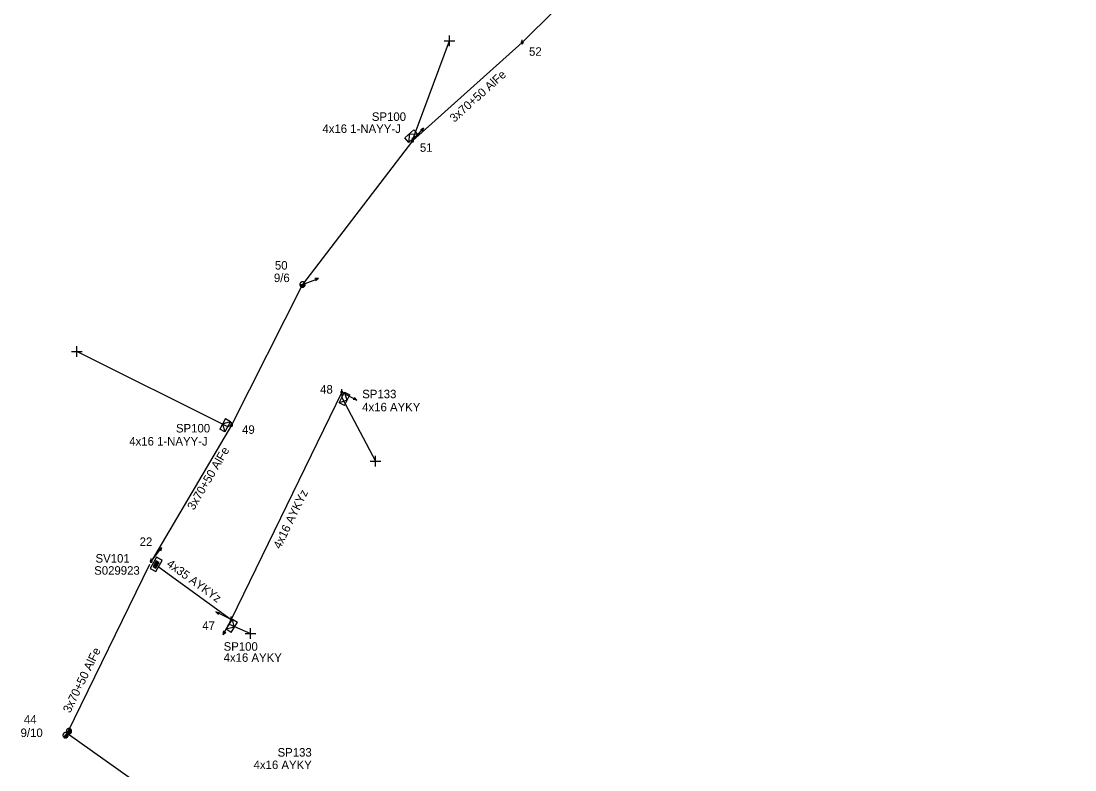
# Model space of a CAD drawing. Extents: x -788458 to -786145, y -1154772 to -1152372.
# Drawn here: x -787342.9 to -787219, y -1152727.5 to -1152639.6 of the extents above; entities that cross this region are included whole.
import ezdxf

# ---------------------------------------------------------------- set-up
doc = ezdxf.new("R2010")
doc.units = 0
for name, color, linetype in [('Vrstva 1', 7, 'Continuous'), ('Vrstva 12', 7, 'Continuous'), ('Vrstva 13', 7, 'Continuous'), ('Vrstva 14', 7, 'Continuous'), ('Vrstva 2', 7, 'Continuous'), ('Vrstva 28', 7, 'Continuous'), ('Vrstva 29', 7, 'Continuous'), ('Vrstva 30', 7, 'Continuous'), ('Vrstva 31', 7, 'Continuous'), ('Vrstva 33', 7, 'Continuous'), ('Vrstva 34', 7, 'Continuous'), ('Vrstva 52', 7, 'Continuous'), ('Vrstva 53', 7, 'Continuous'), ('Vrstva 54', 7, 'Continuous'), ('Vrstva 55', 7, 'Continuous'), ('Vrstva 59', 7, 'Continuous'), ('Vrstva 8', 7, 'Continuous'), ('Vrstva 9', 7, 'Continuous')]:
    doc.layers.add(name, color=color, linetype=linetype)

# ---------------------------------------------------------------- blocks, each defined once
blk = doc.blocks.new('NN440')
at = {"layer": 'Vrstva 2'}
for points in [[(0.63, 0), (0.63, 0.06), (0.62, 0.13), (0.6, 0.19), (0.58, 0.25), (0.55, 0.31), (0.51, 0.37), (0.47, 0.42), (0.42, 0.46), (0.37, 0.51), (0.32, 0.54), (0.26, 0.57), (0.2, 0.59), (0.13, 0.61), (0.07, 0.62), (0, 0.63), (-0.06, 0.62), (-0.13, 0.61), (-0.19, 0.59), (-0.26, 0.57), (-0.31, 0.54), (-0.37, 0.51), (-0.42, 0.46), (-0.47, 0.42), (-0.51, 0.37), (-0.54, 0.31), (-0.57, 0.25), (-0.6, 0.19), (-0.62, 0.13), (-0.63, 0.06), (-0.63, 0), (-0.63, -0.07), (-0.62, -0.14), (-0.6, -0.2), (-0.57, -0.26), (-0.54, -0.32), (-0.51, -0.37), (-0.47, -0.43), (-0.42, -0.47), (-0.37, -0.51), (-0.31, -0.55), (-0.26, -0.58), (-0.19, -0.6), (-0.13, -0.62), (-0.06, -0.63), (0, -0.63), (0.07, -0.63), (0.13, -0.62), (0.2, -0.6), (0.26, -0.58), (0.32, -0.55), (0.37, -0.51), (0.42, -0.47), (0.47, -0.43), (0.51, -0.37), (0.55, -0.32), (0.58, -0.26), (0.6, -0.2), (0.62, -0.14), (0.63, -0.07), (0.63, 0)], [(-0.63, 0), (0.63, 0)], [(-0.6, -0.18), (0.57, -0.18)], [(-0.51, -0.32), (0.5, -0.32)], [(-0.37, -0.47), (0.35, -0.47)]]:
    blk.add_lwpolyline(points, dxfattribs=at)
blk = doc.blocks.new('NN450')
at = {"layer": 'Vrstva 2'}
for points in [[(0, 0), (0, 0.07), (-0.01, 0.13), (-0.03, 0.19), (-0.05, 0.25), (-0.08, 0.31), (-0.12, 0.37), (-0.16, 0.42), (-0.21, 0.46), (-0.26, 0.51), (-0.31, 0.54), (-0.37, 0.57), (-0.43, 0.59), (-0.5, 0.61), (-0.56, 0.62), (-0.63, 0.62), (-0.69, 0.62), (-0.75, 0.61), (-0.82, 0.59), (-0.88, 0.57), (-0.94, 0.54), (-0.99, 0.51), (-1.04, 0.46), (-1.09, 0.42), (-1.13, 0.37), (-1.17, 0.31), (-1.2, 0.25), (-1.22, 0.19), (-1.24, 0.13), (-1.25, 0.07), (-1.25, 0), (-1.25, -0.07), (-1.24, -0.13), (-1.22, -0.19), (-1.2, -0.25), (-1.17, -0.31), (-1.13, -0.37), (-1.09, -0.42), (-1.04, -0.46), (-0.99, -0.51), (-0.94, -0.54), (-0.88, -0.57), (-0.82, -0.59), (-0.75, -0.61), (-0.69, -0.62), (-0.62, -0.63), (-0.56, -0.62), (-0.5, -0.61), (-0.43, -0.59), (-0.37, -0.57), (-0.31, -0.54), (-0.26, -0.51), (-0.21, -0.46), (-0.16, -0.42), (-0.12, -0.37), (-0.08, -0.31), (-0.05, -0.25), (-0.03, -0.19), (-0.01, -0.13), (0, -0.07), (0, 0)], [(1.25, 0), (1.25, 0.07), (1.24, 0.13), (1.22, 0.19), (1.2, 0.25), (1.17, 0.31), (1.13, 0.37), (1.09, 0.42), (1.04, 0.46), (0.99, 0.51), (0.94, 0.54), (0.88, 0.57), (0.82, 0.59), (0.75, 0.61), (0.69, 0.62), (0.62, 0.62), (0.56, 0.62), (0.5, 0.61), (0.43, 0.59), (0.37, 0.57), (0.31, 0.54), (0.26, 0.51), (0.21, 0.46), (0.16, 0.42), (0.12, 0.37), (0.08, 0.31), (0.05, 0.25), (0.03, 0.19), (0.01, 0.13), (0, 0.07), (0, 0), (0, -0.07), (0.01, -0.13), (0.03, -0.19), (0.05, -0.25), (0.08, -0.31), (0.12, -0.37), (0.16, -0.42), (0.21, -0.46), (0.26, -0.51), (0.31, -0.54), (0.37, -0.57), (0.43, -0.59), (0.5, -0.61), (0.56, -0.62), (0.63, -0.63), (0.69, -0.62), (0.75, -0.61), (0.82, -0.59), (0.88, -0.57), (0.94, -0.54), (0.99, -0.51), (1.04, -0.46), (1.09, -0.42), (1.13, -0.37), (1.17, -0.31), (1.2, -0.25), (1.22, -0.19), (1.24, -0.13), (1.25, -0.07), (1.25, 0)], [(-1.25, 0), (1.25, 0)], [(-1.23, -0.16), (-0.02, -0.16)], [(-1.16, -0.32), (-0.09, -0.32)], [(-1.03, -0.47), (-0.22, -0.47)], [(0.02, -0.16), (1.23, -0.16)], [(0.09, -0.32), (1.16, -0.32)], [(0.22, -0.47), (1.03, -0.47)]]:
    blk.add_lwpolyline(points, dxfattribs=at)
blk = doc.blocks.new('NN560')
at = {"layer": 'Vrstva 2'}
for points in [[(2, 0), (1.59, 0.14)], [(0, 0), (2, 0)], [(2, 0), (1.59, -0.13)]]:
    blk.add_lwpolyline(points, dxfattribs=at)
blk = doc.blocks.new('NN800')
at = {"layer": 'Vrstva 1'}
for points in [[(-0.44, 0.44), (0.44, -0.44)], [(-0.44, -0.44), (0.44, 0.44)]]:
    blk.add_lwpolyline(points, dxfattribs=at)
blk = doc.blocks.new('NN620')
at = {"layer": 'Vrstva 8'}
for points in [[(0.75, 0), (-0.75, 0)], [(-0.75, 0), (-0.75, -0.75)], [(0.75, -0.75), (0.75, 0)], [(-0.75, -0.75), (0.75, -0.75)], [(0.37, -0.18), (-0.38, -0.18)], [(-0.38, -0.18), (-0.38, -0.56)], [(-0.38, -0.56), (0.37, -0.56)], [(0.32, -0.23), (-0.33, -0.23)], [(-0.33, -0.23), (-0.33, -0.51)], [(-0.33, -0.51), (0.32, -0.51)], [(0.27, -0.27), (-0.28, -0.27)], [(-0.28, -0.27), (-0.28, -0.46)], [(-0.28, -0.46), (0.27, -0.46)], [(0.23, -0.32), (-0.23, -0.32)], [(-0.23, -0.32), (-0.23, -0.42)], [(-0.23, -0.42), (0.23, -0.42)], [(-0.19, -0.37), (0.19, -0.37)], [(0.23, -0.42), (0.23, -0.32)], [(0.27, -0.46), (0.27, -0.27)], [(0.32, -0.51), (0.32, -0.23)], [(0.37, -0.56), (0.37, -0.18)]]:
    blk.add_lwpolyline(points, dxfattribs=at)
blk = doc.blocks.new('NN630')
at = {"layer": 'Vrstva 9'}
for points in [[(0, -0.7), (-0.7, 0)], [(-0.7, -0.7), (-0.7, 0), (0.7, 0), (0.7, -0.7)], [(-0.7, -0.7), (0.7, -0.7)], [(0, -0.7), (0.7, 0)]]:
    blk.add_lwpolyline(points, dxfattribs=at)
blk = doc.blocks.new('NN500')
at = {"layer": 'Vrstva 2'}
for points in [[(0, -0.24), (0.02, -0.23), (0.05, -0.23), (0.07, -0.22), (0.09, -0.22), (0.12, -0.2), (0.14, -0.19), (0.16, -0.18), (0.17, -0.16), (0.19, -0.14), (0.2, -0.12), (0.21, -0.1), (0.22, -0.07), (0.23, -0.05), (0.23, -0.02), (0.23, 0), (0.23, 0.02), (0.23, 0.05), (0.22, 0.07), (0.21, 0.1), (0.2, 0.12), (0.19, 0.14), (0.17, 0.16), (0.16, 0.17), (0.14, 0.19), (0.12, 0.2), (0.09, 0.21), (0.07, 0.22), (0.05, 0.23), (0.02, 0.23), (0, 0.23), (-0.03, 0.23), (-0.05, 0.23), (-0.07, 0.22), (-0.1, 0.21), (-0.12, 0.2), (-0.14, 0.19), (-0.16, 0.17), (-0.18, 0.16), (-0.19, 0.14), (-0.2, 0.12), (-0.22, 0.1), (-0.22, 0.07), (-0.23, 0.05), (-0.23, 0.02), (-0.24, 0), (-0.23, -0.02), (-0.23, -0.05), (-0.22, -0.07), (-0.22, -0.1), (-0.2, -0.12), (-0.19, -0.14), (-0.18, -0.16), (-0.16, -0.18), (-0.14, -0.19), (-0.12, -0.2), (-0.1, -0.22), (-0.07, -0.22), (-0.05, -0.23), (-0.03, -0.23), (0, -0.24)], [(0, -0.24), (0.02, -0.23), (0.05, -0.23), (0.07, -0.22), (0.09, -0.22), (0.12, -0.2), (0.14, -0.19), (0.16, -0.18), (0.17, -0.16), (0.19, -0.14), (0.2, -0.12), (0.21, -0.1), (0.22, -0.07), (0.23, -0.05), (0.23, -0.02), (0.23, 0), (0.23, 0.02), (0.23, 0.05), (0.22, 0.07), (0.21, 0.1), (0.2, 0.12), (0.19, 0.14), (0.17, 0.16), (0.16, 0.17), (0.14, 0.19), (0.12, 0.2), (0.09, 0.21), (0.07, 0.22), (0.05, 0.23), (0.02, 0.23), (0, 0.23), (-0.03, 0.23), (-0.05, 0.23), (-0.07, 0.22), (-0.1, 0.21), (-0.12, 0.2), (-0.14, 0.19), (-0.16, 0.17), (-0.18, 0.16), (-0.19, 0.14), (-0.2, 0.12), (-0.22, 0.1), (-0.22, 0.07), (-0.23, 0.05), (-0.23, 0.02), (-0.24, 0), (-0.23, -0.02), (-0.23, -0.05), (-0.22, -0.07), (-0.22, -0.1), (-0.2, -0.12), (-0.19, -0.14), (-0.18, -0.16), (-0.16, -0.18), (-0.14, -0.19), (-0.12, -0.2), (-0.1, -0.22), (-0.07, -0.22), (-0.05, -0.23), (-0.03, -0.23), (0, -0.24)], [(0, -0.21), (0.02, -0.2), (0.04, -0.2), (0.06, -0.2), (0.08, -0.19), (0.1, -0.18), (0.12, -0.17), (0.14, -0.15), (0.15, -0.14), (0.16, -0.12), (0.18, -0.1), (0.19, -0.08), (0.19, -0.06), (0.2, -0.04), (0.2, -0.02), (0.2, 0), (0.2, 0.02), (0.2, 0.04), (0.19, 0.06), (0.19, 0.08), (0.18, 0.1), (0.16, 0.12), (0.15, 0.14), (0.14, 0.15), (0.12, 0.17), (0.1, 0.18), (0.08, 0.19), (0.06, 0.19), (0.04, 0.2), (0.02, 0.2), (0, 0.2), (-0.02, 0.2), (-0.04, 0.2), (-0.06, 0.19), (-0.08, 0.19), (-0.1, 0.18), (-0.12, 0.17), (-0.14, 0.15), (-0.15, 0.14), (-0.17, 0.12), (-0.18, 0.1), (-0.19, 0.08), (-0.2, 0.06), (-0.2, 0.04), (-0.21, 0.02), (-0.21, 0), (-0.21, -0.02), (-0.2, -0.04), (-0.2, -0.06), (-0.19, -0.08), (-0.18, -0.1), (-0.17, -0.12), (-0.15, -0.14), (-0.14, -0.15), (-0.12, -0.17), (-0.1, -0.18), (-0.08, -0.19), (-0.06, -0.2), (-0.04, -0.2), (-0.02, -0.2), (0, -0.21)], [(0, -0.18), (0.02, -0.18), (0.04, -0.17), (0.05, -0.17), (0.07, -0.16), (0.09, -0.15), (0.1, -0.14), (0.12, -0.13), (0.13, -0.12), (0.14, -0.1), (0.15, -0.09), (0.16, -0.07), (0.17, -0.05), (0.17, -0.04), (0.17, -0.02), (0.17, 0), (0.17, 0.02), (0.17, 0.04), (0.17, 0.05), (0.16, 0.07), (0.15, 0.09), (0.14, 0.1), (0.13, 0.12), (0.12, 0.13), (0.1, 0.14), (0.09, 0.15), (0.07, 0.16), (0.05, 0.17), (0.04, 0.17), (0.02, 0.17), (0, 0.18), (-0.02, 0.17), (-0.04, 0.17), (-0.06, 0.17), (-0.07, 0.16), (-0.09, 0.15), (-0.1, 0.14), (-0.12, 0.13), (-0.13, 0.12), (-0.14, 0.1), (-0.15, 0.09), (-0.16, 0.07), (-0.17, 0.05), (-0.17, 0.04), (-0.18, 0.02), (-0.18, 0), (-0.18, -0.02), (-0.17, -0.04), (-0.17, -0.05), (-0.16, -0.07), (-0.15, -0.09), (-0.14, -0.1), (-0.13, -0.12), (-0.12, -0.13), (-0.1, -0.14), (-0.09, -0.15), (-0.07, -0.16), (-0.06, -0.17), (-0.04, -0.17), (-0.02, -0.18), (0, -0.18)], [(0, -0.15), (0.01, -0.15), (0.03, -0.14), (0.04, -0.14), (0.06, -0.13), (0.07, -0.13), (0.08, -0.12), (0.1, -0.11), (0.11, -0.1), (0.12, -0.09), (0.13, -0.07), (0.13, -0.06), (0.14, -0.05), (0.14, -0.03), (0.14, -0.02), (0.14, 0), (0.14, 0.01), (0.14, 0.03), (0.14, 0.04), (0.13, 0.06), (0.13, 0.07), (0.12, 0.09), (0.11, 0.1), (0.1, 0.11), (0.08, 0.12), (0.07, 0.13), (0.06, 0.13), (0.04, 0.14), (0.03, 0.14), (0.01, 0.14), (0, 0.15), (-0.02, 0.14), (-0.03, 0.14), (-0.05, 0.14), (-0.06, 0.13), (-0.07, 0.13), (-0.09, 0.12), (-0.1, 0.11), (-0.11, 0.1), (-0.12, 0.09), (-0.13, 0.07), (-0.13, 0.06), (-0.14, 0.04), (-0.14, 0.03), (-0.15, 0.01), (-0.15, 0), (-0.15, -0.02), (-0.14, -0.03), (-0.14, -0.05), (-0.13, -0.06), (-0.13, -0.07), (-0.12, -0.09), (-0.11, -0.1), (-0.1, -0.11), (-0.09, -0.12), (-0.07, -0.13), (-0.06, -0.13), (-0.05, -0.14), (-0.03, -0.14), (-0.02, -0.15), (0, -0.15)], [(0, -0.12), (0.01, -0.12), (0.02, -0.11), (0.03, -0.11), (0.05, -0.11), (0.06, -0.1), (0.07, -0.09), (0.08, -0.09), (0.09, -0.08), (0.09, -0.07), (0.1, -0.06), (0.11, -0.05), (0.11, -0.04), (0.11, -0.02), (0.11, -0.01), (0.12, 0), (0.11, 0.01), (0.11, 0.02), (0.11, 0.04), (0.11, 0.05), (0.1, 0.06), (0.09, 0.07), (0.09, 0.08), (0.08, 0.09), (0.07, 0.09), (0.06, 0.1), (0.05, 0.11), (0.03, 0.11), (0.02, 0.11), (0.01, 0.12), (0, 0.12), (-0.01, 0.12), (-0.03, 0.11), (-0.04, 0.11), (-0.05, 0.11), (-0.06, 0.1), (-0.07, 0.09), (-0.08, 0.09), (-0.09, 0.08), (-0.1, 0.07), (-0.1, 0.06), (-0.11, 0.05), (-0.11, 0.04), (-0.12, 0.02), (-0.12, 0.01), (-0.12, 0), (-0.12, -0.01), (-0.12, -0.02), (-0.11, -0.04), (-0.11, -0.05), (-0.1, -0.06), (-0.1, -0.07), (-0.09, -0.08), (-0.08, -0.09), (-0.07, -0.09), (-0.06, -0.1), (-0.05, -0.11), (-0.04, -0.11), (-0.03, -0.11), (-0.01, -0.12), (0, -0.12)], [(0, -0.09), (0.01, -0.09), (0.02, -0.09), (0.03, -0.08), (0.03, -0.08), (0.04, -0.08), (0.05, -0.07), (0.06, -0.07), (0.06, -0.06), (0.07, -0.05), (0.07, -0.04), (0.08, -0.04), (0.08, -0.03), (0.08, -0.02), (0.09, -0.01), (0.09, 0), (0.09, 0.01), (0.08, 0.02), (0.08, 0.03), (0.08, 0.03), (0.07, 0.04), (0.07, 0.05), (0.06, 0.06), (0.06, 0.06), (0.05, 0.07), (0.04, 0.07), (0.03, 0.08), (0.03, 0.08), (0.02, 0.08), (0.01, 0.09), (0, 0.09), (-0.01, 0.09), (-0.02, 0.08), (-0.03, 0.08), (-0.04, 0.08), (-0.04, 0.07), (-0.05, 0.07), (-0.06, 0.06), (-0.07, 0.06), (-0.07, 0.05), (-0.08, 0.04), (-0.08, 0.03), (-0.08, 0.03), (-0.09, 0.02), (-0.09, 0.01), (-0.09, 0), (-0.09, -0.01), (-0.09, -0.02), (-0.08, -0.03), (-0.08, -0.04), (-0.08, -0.04), (-0.07, -0.05), (-0.07, -0.06), (-0.06, -0.07), (-0.05, -0.07), (-0.04, -0.08), (-0.04, -0.08), (-0.03, -0.08), (-0.02, -0.09), (-0.01, -0.09), (0, -0.09)], [(0, -0.06), (0, -0.06), (0.01, -0.06), (0.02, -0.05), (0.02, -0.05), (0.03, -0.05), (0.03, -0.05), (0.04, -0.04), (0.04, -0.04), (0.05, -0.03), (0.05, -0.03), (0.05, -0.02), (0.05, -0.02), (0.05, -0.01), (0.06, -0.01), (0.06, 0), (0.06, 0.01), (0.05, 0.01), (0.05, 0.02), (0.05, 0.02), (0.05, 0.03), (0.05, 0.03), (0.04, 0.04), (0.04, 0.04), (0.03, 0.05), (0.03, 0.05), (0.02, 0.05), (0.02, 0.05), (0.01, 0.06), (0, 0.06), (0, 0.06), (-0.01, 0.06), (-0.01, 0.06), (-0.02, 0.05), (-0.02, 0.05), (-0.03, 0.05), (-0.03, 0.05), (-0.04, 0.04), (-0.04, 0.04), (-0.05, 0.03), (-0.05, 0.03), (-0.05, 0.02), (-0.06, 0.02), (-0.06, 0.01), (-0.06, 0.01), (-0.06, 0), (-0.06, -0.01), (-0.06, -0.01), (-0.06, -0.02), (-0.05, -0.02), (-0.05, -0.03), (-0.05, -0.03), (-0.04, -0.04), (-0.04, -0.04), (-0.03, -0.05), (-0.03, -0.05), (-0.02, -0.05), (-0.02, -0.05), (-0.01, -0.06), (-0.01, -0.06), (0, -0.06)], [(0, -0.03), (0, -0.03), (0, -0.03), (0.01, -0.03), (0.01, -0.03), (0.01, -0.02), (0.02, -0.02), (0.02, -0.02), (0.02, -0.02), (0.02, -0.02), (0.02, -0.01), (0.02, -0.01), (0.03, -0.01), (0.03, -0.01), (0.03, 0), (0.03, 0), (0.03, 0), (0.03, 0.01), (0.03, 0.01), (0.02, 0.01), (0.02, 0.01), (0.02, 0.02), (0.02, 0.02), (0.02, 0.02), (0.02, 0.02), (0.01, 0.02), (0.01, 0.02), (0.01, 0.03), (0, 0.03), (0, 0.03), (0, 0.03), (0, 0.03), (-0.01, 0.03), (-0.01, 0.03), (-0.01, 0.02), (-0.02, 0.02), (-0.02, 0.02), (-0.02, 0.02), (-0.02, 0.02), (-0.02, 0.02), (-0.03, 0.01), (-0.03, 0.01), (-0.03, 0.01), (-0.03, 0.01), (-0.03, 0), (-0.03, 0), (-0.03, 0), (-0.03, -0.01), (-0.03, -0.01), (-0.03, -0.01), (-0.03, -0.01), (-0.02, -0.02), (-0.02, -0.02), (-0.02, -0.02), (-0.02, -0.02), (-0.02, -0.02), (-0.01, -0.03), (-0.01, -0.03), (-0.01, -0.03), (0, -0.03), (0, -0.03)], [(0.23, 0), (0.7, 0)]]:
    blk.add_lwpolyline(points, dxfattribs=at)

msp = doc.modelspace()

# ---------------------------------------------------------------- linework, layer by layer
at = {"layer": 'Vrstva 1'}
for points in [[(-787242.14, -1152598.03), (-787250.54, -1152608.84), (-787264.71, -1152622.95), (-787283.97, -1152642.09), (-787296.85, -1152653.64), (-787309.78, -1152670.5), (-787318.12, -1152687.04), (-787327.56, -1152703.03)], [(-787327.74, -1152703.4), (-787337.42, -1152723.22), (-787317.82, -1152737.16), (-787292.34, -1152746.43), (-787268.1, -1152755.42), (-787235.6, -1152767.7), (-787219.01, -1152771.91)]]:
    msp.add_lwpolyline(points, dxfattribs=at)
at = {"layer": 'Vrstva 52'}
for points in [[(-787305.16, -1152683.16), (-787318.17, -1152709.87)], [(-787305.16, -1152683.16), (-787305.15, -1152683.78)], [(-787326.75, -1152703.62), (-787318.17, -1152709.87)], [(-787318.17, -1152709.87), (-787318.39, -1152710.41)]]:
    msp.add_lwpolyline(points, dxfattribs=at)
at = {"layer": 'Vrstva 59'}
for points in [[(-787296.76, -1152653.33), (-787292.5, -1152641.88)], [(-787318.56, -1152687.21), (-787336.31, -1152678.38)], [(-787305.15, -1152683.78), (-787301.19, -1152691.25)], [(-787318.39, -1152710.41), (-787315.88, -1152711.5)]]:
    msp.add_lwpolyline(points, dxfattribs=at)
at = {"layer": 'Vrstva 8'}
for points in [[(-787296.85, -1152653.64), (-787296.76, -1152653.33)], [(-787318.12, -1152687.04), (-787318.56, -1152687.21)]]:
    msp.add_lwpolyline(points, dxfattribs=at)

# ---------------------------------------------------------------- block references
at = {"layer": 'Vrstva 13', "xscale": 0.5, "yscale": 0.5}
for name, p, rotation in [('NN500', (-787283.97, -1152642.09), 90), ('NN500', (-787296.85, -1152653.64), 90), ('NN500', (-787305.16, -1152683.16), 90), ('NN500', (-787318.12, -1152687.04), 90), ('NN500', (-787327.56, -1152703.03), 90), ('NN500', (-787318.17, -1152709.87), 90), ('NN450', (-787337.42, -1152723.22), 50.083859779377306)]:
    msp.add_blockref(name, p, dxfattribs=dict(at, rotation=rotation))
at = {"layer": 'Vrstva 13'}
for p, rotation in [((-787296.85, -1152653.64), 49.15744721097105), ((-787309.78, -1152670.5), 20.765594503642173), ((-787305.16, -1152683.16), -27.55940277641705), ((-787327.56, -1152703.03), 52.25572784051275), ((-787318.17, -1152709.87), 152.7021055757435), ((-787318.17, -1152709.87), -118.19497772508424)]:
    msp.add_blockref('NN560', p, dxfattribs=dict(at, rotation=rotation))
at = {"layer": 'Vrstva 13', "xscale": 0.5, "yscale": 0.5}
msp.add_blockref('NN440', (-787309.78, -1152670.5), dxfattribs=at)
at = {"layer": 'Vrstva 28', "rotation": 60.83553524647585}
msp.add_blockref('NN620', (-787327.31, -1152703.21), dxfattribs=at)
at = {"layer": 'Vrstva 31'}
for p, rotation in [((-787296.76, -1152653.33), -137.59186666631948), ((-787305.15, -1152683.78), 62.641062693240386), ((-787318.56, -1152687.21), -118.5596205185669), ((-787318.39, -1152710.41), 58.28018474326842)]:
    msp.add_blockref('NN630', p, dxfattribs=dict(at, rotation=rotation))
at = {"layer": 'Vrstva 34'}
for p, rotation in [((-787292.5, -1152641.88), 45), ((-787336.31, -1152678.38), 45.00000009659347), ((-787301.19, -1152691.25), 44.99999995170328), ((-787315.88, -1152711.5), 45)]:
    msp.add_blockref('NN800', p, dxfattribs=dict(at, rotation=rotation))

# ---------------------------------------------------------------- texts
at = {"layer": 'Vrstva 12'}
for s, p in [('9/6', (-787313.14, -1152670.22)), ('9/10', (-787342.91, -1152723.67))]:
    msp.add_text(s, height=1, dxfattribs=at).set_placement(p)
at = {"layer": 'Vrstva 14'}
for s, p in [('52', (-787283.16, -1152643.63)), ('51', (-787295.98, -1152654.91)), ('50', (-787313.02, -1152668.75)), ('48', (-787307.71, -1152683.32)), ('49', (-787316.88, -1152688.05)), ('22', (-787328.92, -1152701.22)), ('47', (-787321.56, -1152711.08)), ('44', (-787342.52, -1152722.1))]:
    msp.add_text(s, height=1, dxfattribs=at).set_placement(p)
at = {"layer": 'Vrstva 2'}
for rotation, p in [(41.949, (-787291.93, -1152651.51)), (59.444, (-787322.54, -1152697.09)), (63.971, (-787337.09, -1152720.92))]:
    msp.add_text('3x70+50 AlFe', height=1, rotation=rotation, dxfattribs=at).set_placement(p)
at = {"layer": 'Vrstva 29'}
msp.add_text('S029923', height=1, dxfattribs=at).set_placement((-787334.26, -1152704.6))
at = {"layer": 'Vrstva 30'}
msp.add_text('SV101', height=1, dxfattribs=at).set_placement((-787334.1, -1152703.18))
at = {"layer": 'Vrstva 33'}
for s, p in [('SP100', (-787301.63, -1152651.28)), ('SP133', (-787302.76, -1152683.87)), ('SP100', (-787324.65, -1152687.89)), ('SP100', (-787319.05, -1152713.53)), ('SP133', (-787312.71, -1152725.97))]:
    msp.add_text(s, height=1, dxfattribs=at).set_placement(p)
at = {"layer": 'Vrstva 53'}
for s, rotation, p in [('4x16 AYKYz', 64.03, (-787312.38, -1152701.65)), ('4x35 AYKYz', 323.929, (-787325.84, -1152703.52))]:
    msp.add_text(s, height=1, rotation=rotation, dxfattribs=at).set_placement(p)
at = {"layer": 'Vrstva 54'}
for rotation, p in [(359.887, (-787302.77, -1152685.4)), (359.887, (-787319.05, -1152714.83)), (359.866, (-787315.53, -1152727.43))]:
    msp.add_text('4x16 AYKY', height=1, rotation=rotation, dxfattribs=at).set_placement(p)
at = {"layer": 'Vrstva 55'}
msp.add_text('4x16 1-NAYY-J', height=1, dxfattribs=at).set_placement((-787307.44, -1152652.7))
msp.add_text('4x16 1-NAYY-J', height=1, rotation=359.942, dxfattribs=at).set_placement((-787330.14, -1152689.42))

doc.saveas('drawing.dxf')
